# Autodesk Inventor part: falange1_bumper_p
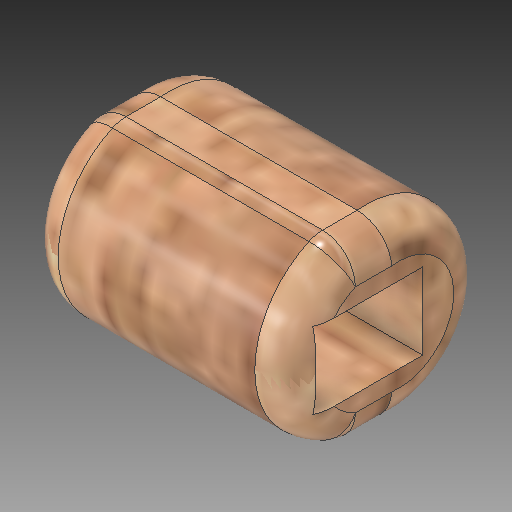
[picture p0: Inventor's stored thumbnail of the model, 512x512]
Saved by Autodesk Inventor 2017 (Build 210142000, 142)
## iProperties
Created: 2017-05
Part Number: falange1_bumper_p
Material: Generic
Document SubType Name: Modeling
Designer: alez_
Density: 1 g/cm^3
Appearance: Default
Author: alez_
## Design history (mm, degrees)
derived "Falange_1_bumper.ipt" dims "d0" = 9
feature "Solid1::Falange_1_bumper.ipt" dims "d0" = 9
tag "TaggingFeature1"
body "Solid1"
